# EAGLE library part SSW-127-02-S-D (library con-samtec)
THROUGH-HOLE .025" SQ POST SOCKET Source: Samtec SSW.pdf
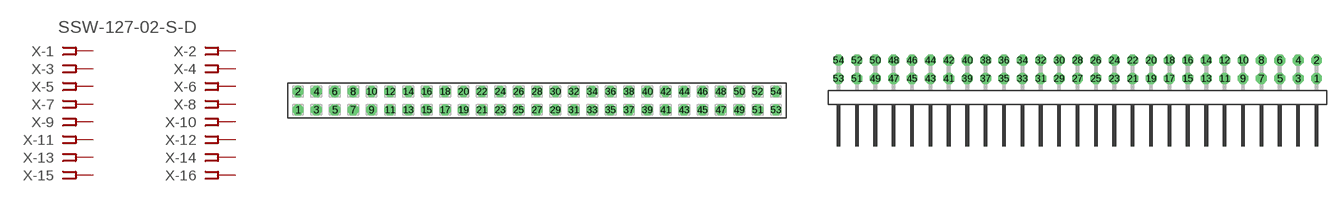
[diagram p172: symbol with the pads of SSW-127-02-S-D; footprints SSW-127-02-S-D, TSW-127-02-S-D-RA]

Designator prefix X; gates -1=FPINV -2=FPIN -3=FPIN -4=FPIN -5=FPIN -6=FPIN -7=FPIN -8=FPIN -9=FPIN -10=FPIN -11=FPIN -12=FPIN -13=FPIN -14=FPIN -15=FPIN -16=FPIN -17=FPIN -18=FPIN -19=FPIN -20=FPIN -21=FPIN -22=FPIN -23=FPIN -24=FPIN -25=FPIN -26=FPIN -27=FPIN -28=FPIN -29=FPIN -30=FPIN -31=FPIN -32=FPIN -33=FPIN -34=FPIN -35=FPIN -36=FPIN -37=FPIN -38=FPIN -39=FPIN -40=FPIN -41=FPIN -42=FPIN -43=FPIN -44=FPIN -45=FPIN -46=FPIN -47=FPIN -48=FPIN -49=FPIN -50=FPIN -51=FPIN -52=FPIN -53=FPIN -54=FPIN

## SSW-127-02-S-D (MPN: SSW-127-02-S-D; OC_FARNELL: unknown; OC_NEWARK: 11P9757)  [SSW-127-02-S-D]
1  -1:1  pas
2  -2:1  pas
3  -3:1  pas
4  -4:1  pas
5  -5:1  pas
6  -6:1  pas
7  -7:1  pas
8  -8:1  pas
9  -9:1  pas
10  -10:1  pas
11  -11:1  pas
12  -12:1  pas
13  -13:1  pas
14  -14:1  pas
15  -15:1  pas
16  -16:1  pas
17  -17:1  pas
18  -18:1  pas
19  -19:1  pas
20  -20:1  pas
21  -21:1  pas
22  -22:1  pas
23  -23:1  pas
24  -24:1  pas
25  -25:1  pas
26  -26:1  pas
27  -27:1  pas
28  -28:1  pas
29  -29:1  pas
30  -30:1  pas
31  -31:1  pas
32  -32:1  pas
33  -33:1  pas
34  -34:1  pas
35  -35:1  pas
36  -36:1  pas
37  -37:1  pas
38  -38:1  pas
39  -39:1  pas
40  -40:1  pas
41  -41:1  pas
42  -42:1  pas
43  -43:1  pas
44  -44:1  pas
45  -45:1  pas
46  -46:1  pas
47  -47:1  pas
48  -48:1  pas
49  -49:1  pas
50  -50:1  pas
51  -51:1  pas
52  -52:1  pas
53  -53:1  pas
54  -54:1  pas

## SSW-127-02-S-D-RA (MPN: SSW-127-02-S-D-RA; OC_FARNELL: unknown; OC_NEWARK: 11P9758)  [TSW-127-02-S-D-RA]
Pads as for SSW-127-02-S-D

## Footprint SSW-127-02-S-D (pad centres in mm)
THROUGH-HOLE .025" SQ POST SOCKET Source: Samtec SSW.pdf
drill 1 pad 1.5 octagon: 1 -33.02,-1.27; 2 -33.02,1.27; 3 -30.48,-1.27; 4 -30.48,1.27; 5 -27.94,-1.27; 6 -27.94,1.27; 7 -25.4,-1.27; 8 -25.4,1.27; 9 -22.86,-1.27; 10 -22.86,1.27; 11 -20.32,-1.27; 12 -20.32,1.27; 13 -17.78,-1.27; 14 -17.78,1.27; 15 -15.24,-1.27; 16 -15.24,1.27; 17 -12.7,-1.27; 18 -12.7,1.27; 19 -10.16,-1.27; 20 -10.16,1.27; 21 -7.62,-1.27; 22 -7.62,1.27; 23 -5.08,-1.27; 24 -5.08,1.27; 25 -2.54,-1.27; 26 -2.54,1.27; 27 0,-1.27; 28 0,1.27; 29 2.54,-1.27; 30 2.54,1.27; 31 5.08,-1.27; 32 5.08,1.27; 33 7.62,-1.27; 34 7.62,1.27; 35 10.16,-1.27; 36 10.16,1.27; 37 12.7,-1.27; 38 12.7,1.27; 39 15.24,-1.27; 40 15.24,1.27; 41 17.78,-1.27; 42 17.78,1.27; 43 20.32,-1.27; 44 20.32,1.27; 45 22.86,-1.27; 46 22.86,1.27; 47 25.4,-1.27; 48 25.4,1.27; 49 27.94,-1.27; 50 27.94,1.27; 51 30.48,-1.27; 52 30.48,1.27; 53 33.02,-1.27; 54 33.02,1.27

## Footprint TSW-127-02-S-D-RA (pad centres in mm)
THROUGH-HOLE .025" SQ POST HEADER Source: Samtec TSW.pdf
drill 1 pad 1.5 octagon: 1 33.02,1.524; 2 33.02,4.064; 3 30.48,1.524; 4 30.48,4.064; 5 27.94,1.524; 6 27.94,4.064; 7 25.4,1.524; 8 25.4,4.064; 9 22.86,1.524; 10 22.86,4.064; 11 20.32,1.524; 12 20.32,4.064; 13 17.78,1.524; 14 17.78,4.064; 15 15.24,1.524; 16 15.24,4.064; 17 12.7,1.524; 18 12.7,4.064; 19 10.16,1.524; 20 10.16,4.064; 21 7.62,1.524; 22 7.62,4.064; 23 5.08,1.524; 24 5.08,4.064; 25 2.54,1.524; 26 2.54,4.064; 27 0,1.524; 28 0,4.064; 29 -2.54,1.524; 30 -2.54,4.064; 31 -5.08,1.524; 32 -5.08,4.064; 33 -7.62,1.524; 34 -7.62,4.064; 35 -10.16,1.524; 36 -10.16,4.064; 37 -12.7,1.524; 38 -12.7,4.064; 39 -15.24,1.524; 40 -15.24,4.064; 41 -17.78,1.524; 42 -17.78,4.064; 43 -20.32,1.524; 44 -20.32,4.064; 45 -22.86,1.524; 46 -22.86,4.064; 47 -25.4,1.524; 48 -25.4,4.064; 49 -27.94,1.524; 50 -27.94,4.064; 51 -30.48,1.524; 52 -30.48,4.064; 53 -33.02,1.524; 54 -33.02,4.064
